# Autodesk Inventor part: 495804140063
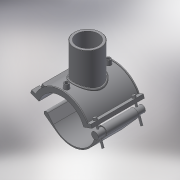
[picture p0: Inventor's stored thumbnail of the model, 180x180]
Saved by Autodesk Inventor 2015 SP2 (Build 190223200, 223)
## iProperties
Created: 2017-07
Part Number: 495804140063
Material: Generic
Description: PLASSON BRANCH SADDLE 140-63
Document SubType Name: Modeling
Designer: KIM
Density: 1 g/cm^3
Appearance: Default
Author: KIM
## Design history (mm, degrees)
derived "495804.ipt"
feature "Solid1::495804.ipt"
feature "Solid2::495804.ipt"
tag "TaggingFeature1"
body "Solid1"
body "Solid2"
other parameters: "d3" = 35, "d4" = 118, "d5" = 0, "d6" = 0.1, "d8" = 0, "d19" = 6, "d20" = 6, "d21" = 70.8, "d23" = 0, "d24" = 35.4, "d26" = 0, "d27" = 3, "d28" = 3, "d29" = 3, "d30" = 46.66667, "d31" = 6, "d32" = 0, "d33" = 0, "d34" = 0.6, "d40" = 82.16, "d41" = 69.3, "d43" = 0, "d45" = 0, "d47" = 173, "d48" = 63, "d50" = 0, "d70" = 15, "d72" = 0, "d73" = 6, "d75" = 5, "d76" = 0, "d77" = 7, "d79" = 15, "d80" = 47.2, "d82" = 5 deg, "d84" = 4, "d85" = 14, "d86" = 0, "d87" = 3, "d88" = 0, "d89" = 1, "d90" = 1, "d91" = 94.4, "d92" = 0, "d93" = 0.5, "d94" = 73.68421, "d96" = 161.16, "d97" = 2.36, "d98" = 0, "d102" = 1.89, "d103" = 50.4, "d105" = 0, "d109" = -31.33333, "d117" = 0.63, "d120" = 140 deg, "d121" = 24.228, "d122" = 20 deg, "d123" = 316, "d124" = 94.8, "d126" = 0, "d143" = 147, "d150" = 25.2, "d159" = 3.6, "d161" = 3.5, "d162" = 70.8, "d163" = 0, "d167" = 28, "d168" = 71.81818, "d173" = 1, "d176" = 20 deg, "d177" = 9.8, "d178" = 18, "d180" = 0, "d185" = 38.35, "d186" = 38.35, "d187" = 79, "d188" = 5.4, "d189" = 9.8, "d190" = 0, "d191" = 118.5, "d200" = 9, "d202" = 0, "d216" = 106.2, "d217" = 0, "d221" = 43.66, "d222" = 9.8, "d223" = 5.88, "d225" = 5.88, "d227" = 20.16, "d230" = 86.8, "d236" = 20 deg, "d237" = 86, "d238" = 20 deg, "d239" = 9.8, "H_" = 94, "L_" = 118, "d_t" = 6, "d_1" = 63, "H_1" = 85, "d1" = 158, "d148" = 3.5, "d160" = 3.5
